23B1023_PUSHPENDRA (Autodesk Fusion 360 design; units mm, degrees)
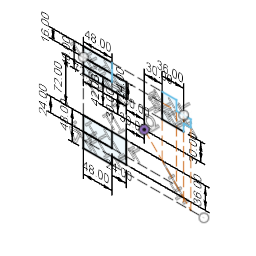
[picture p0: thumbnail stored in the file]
sketch "Sketch1" plane through (0, 0, 0) normal (0, 1, 0) x axis (1, 0, 0)
  line L1 (-102, -30) -> (-30, -30)
  line L2 (-30, -54) -> (-30, -30)
  line L3 (-102, -70) -> (-102, -30)
  line L4 (-53.8889, -70) -> (-102, -70)
  line L5 (-53.8889, -54) -> (-53.8889, -70)
  line L6 (-30, -54) -> (-53.8889, -54)
  line L7 (-101.8889, -54) -> (-53.8889, -54)
  line L8 (-54, -42) -> (-53.8889, -54)
  line L9 (-102, -42) -> (-54, -42)
  line L10 (-30, 30) -> (-30, -30)
  line L11 (-102, 30) -> (-102, -30)
  line L12 (-54, 30) -> (-54, -42)
  line L13 (-30, 30) -> (-102, 30)
  line L14 (-102, 78) -> (-102, 30)
  line L15 (-54, 54) -> (-54, 30)
  line L16 (-54, 78) -> (-102, 78)
  line L17 (-30, 66) -> (-30, 30)
  line L18 (-54, 66) -> (-54, 78)
  line L19 (-30, 66) -> (-54, 66)
  line L20 (-102, 66) -> (-54, 66)
  line L21 (-102, 54) -> (-54, 54)
  line L22 (100, 78) -> (-54, 78)
  line L23 (54, -70) -> (30, -70)
  line L24 (54, -54) -> (54, -70)
  line L25 (78.101, -54) -> (54, -54)
  line L26 (66, -30) -> (30, -30)
  line L27 (78.101, -42) -> (78.101, -54)
  line L28 (66, -30) -> (66, -42)
  line L29 (78.101, -42) -> (66, -42)
  line L30 (66, -54) -> (66, -42)
  line L31 (54, -54) -> (30, -54)
  line L32 (30, -30) -> (30, -70)
  line L33 (30, -70) -> (-53.8889, -70)
  line L34 (30, -54) -> (-30, -54)
  line L35 (30, -30) -> (-30, -30)
  line L36 (78.101, 78) -> (78.101, -42)
  line L37 (66, 78) -> (66, -30)
  line L38 (66, 66) -> (-30, 66)
  line L39 (54, 54) -> (-54, 54)
  line L40 (54, 54) -> (54, -54)
  line L41 (78.101, 78) -> (0, 0)
  line L42 (30.0388, 30) -> (-30, 30)
  arc A1 centre (46368.5478, -30) radius 46338.5478 clockwise from (30, -30) to (30.0388, 30)
  point P10 (-102, -42)
  point P20 (-102, 66)
  point P21 (-102, 54)
  point P33 (78.101, 78)
  point P34 (66, 78)
  point P35 (66, 66)
  point P1 (0, 0)
  point P37 (0, 0)
  point P38 (30.0388, 30)
  point P2 (-30, -30)
  point P3 (-102, -30)
  point P4 (-30, -54)
  point P7 (-53.8889, -54)
  point P8 (-101.8889, -54)
  point P5 (-102, -70)
  point P14 (-54, 30)
  point P16 (-54, 54)
  point P11 (-30, 30)
  point P18 (-30, 66)
  point P19 (-54, 66)
  point P13 (-102, 30)
  point P15 (-102, 78)
  point P9 (-54, -42)
  point P12 (30, -30)
  point P27 (66, -30)
  point P6 (-53.8889, -70)
  horizontal L1
  perpendicular L1 L2
  perpendicular L1 L3
  perpendicular L3 L4
  perpendicular L4 L5
  perpendicular L3 L7
  coincident L3 P10
  perpendicular L3 L9
  perpendicular L1 L10
  perpendicular L1 L11
  perpendicular L9 L12
  perpendicular L10 L13
  perpendicular L13 L14
  perpendicular L13 L15
  perpendicular L14 L16
  perpendicular L16 L18
  perpendicular L17 L19
  coincident L14 P20
  perpendicular L14 L20
  midpoint L14 P21
  perpendicular L14 L21
  perpendicular L18 L22
  perpendicular L23 L24
  perpendicular L24 L25
  perpendicular L25 L27
  perpendicular L26 L28
  perpendicular L27 L29
  perpendicular L25 L30
  perpendicular L26 L32
  perpendicular L32 L33
  perpendicular L32 L34
  perpendicular L32 L35
  coincident L22 P33
  perpendicular L22 L36
  coincident L22 P34
  perpendicular L22 L37
  coincident L37 P35
  perpendicular L37 L38
  perpendicular L17 L39
  perpendicular L39 L40
  coincident P1 P37
  coincident L41 P38
  perpendicular L17 L42
  tangent L32 A1
  dimension "d1" distance P2 P3 = 72
  dimension "d2" distance P2 P4 = 24
  dimension "d6" distance P7 P8 = 48
  dimension "d17" distance P3 P5 = 40
  dimension "d28" distance P1 L2 = 30
  dimension "d29" distance P1 L1 = 30
  dimension "d30" distance P1 L9 = 42
  dimension "d37" distance P14 P16 = 24
  dimension "d38" distance P11 P18 = 36
  dimension "d39" distance P1 L17 = 30
  dimension "d40" distance P18 P19 = 24
  dimension "d41" distance P13 P15 = 48
  dimension "d42" distance P16 P21 = 48
  dimension "d43" distance P9 P14 = 72
  dimension "d46" distance P12 P27 = 36
  dimension "d54" distance P1 L26 = 30
  dimension "d57" distance P1 L32 = 30
  dimension "d59" distance P6 P7 = 16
